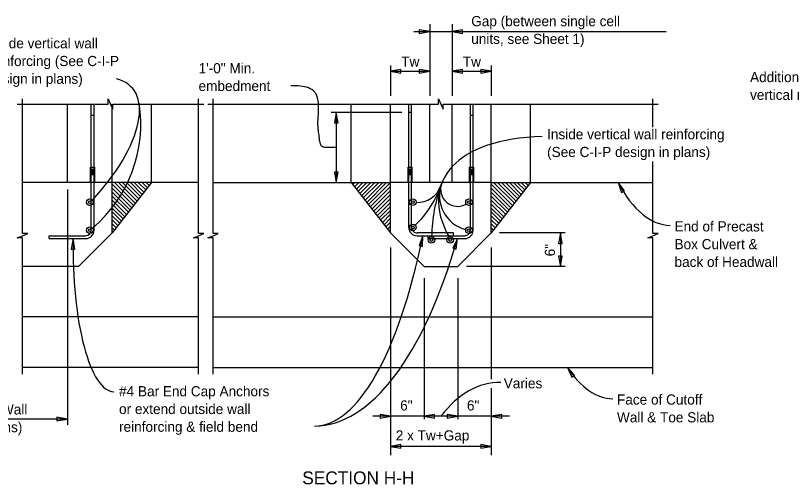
# Model space of a CAD drawing. Extents: x 10605.2 to 10672.7, y 76423.8 to 76450.2.
# Drawn here: x 10627.65 to 10639.2, y 76440.07 to 76447.04 of the extents above; entities that cross this region are included whole.
import ezdxf

# ---------------------------------------------------------------- set-up
doc = ezdxf.new("R2010")
doc.units = 0
for name, color, linetype in [('AdhocPoint_dp', 7, 'Continuous'), ('Patterning', 7, 'Continuous'), ('PlotBorder_dp', 7, 'Continuous'), ('SheetBorder_dp', 7, 'Continuous'), ('SheetLines_dp', 7, 'Continuous'), ('TextMisc', 7, 'Continuous')]:
    doc.layers.add(name, color=color, linetype=linetype)

msp = doc.modelspace()

# ---------------------------------------------------------------- linework, layer by layer
at = {"layer": 'AdhocPoint_dp'}
for p, q in [((10633.814, 76446.912), (10633.814, 76445.847)), ((10634.148, 76446.912), (10634.148, 76445.847)), ((10633.578, 76446.802), (10633.814, 76446.802)), ((10633.814, 76446.802), (10634.148, 76446.802)), ((10634.148, 76446.802), (10637.331, 76446.802)), ((10633.231, 76446.298), (10633.231, 76445.847)), ((10634.731, 76446.298), (10634.731, 76445.847)), ((10633.231, 76446.214), (10633.814, 76446.214)), ((10634.148, 76446.214), (10634.731, 76446.214)), ((10637.136, 76445.379), (10637.136, 76445.802)), ((10633.402, 76445.6), (10632.347, 76445.6)), ((10632.424, 76445.6), (10632.424, 76444.558)), ((10628.424, 76444.453), (10628.424, 76440.952)), ((10635.831, 76443.808), (10634.854, 76443.808)), ((10635.759, 76443.808), (10635.759, 76443.308)), ((10633.231, 76443.593), (10633.231, 76440.503)), ((10634.731, 76443.593), (10634.731, 76441.633)), ((10635.831, 76443.308), (10634.362, 76443.308)), ((10633.731, 76443.135), (10633.731, 76441.038)), ((10634.231, 76443.135), (10634.231, 76441.038)), ((10634.731, 76441.498), (10634.731, 76440.503)), ((10633.231, 76441.082), (10632.968, 76441.082)), ((10633.731, 76441.082), (10633.231, 76441.082)), ((10634.231, 76441.082), (10633.731, 76441.082)), ((10634.731, 76441.082), (10634.231, 76441.082)), ((10635.004, 76441.082), (10634.731, 76441.082)), ((10628.422, 76441.04), (10626, 76441.04)), ((10634.731, 76440.633), (10633.231, 76440.633))]:
    msp.add_line(p, q, dxfattribs=at)
for points in [[(10633.814, 76446.802), (10633.658, 76446.828), (10633.658, 76446.775)], [(10634.148, 76446.802), (10634.304, 76446.775), (10634.304, 76446.828)], [(10633.231, 76446.214), (10633.387, 76446.187), (10633.387, 76446.24)], [(10633.814, 76446.214), (10633.658, 76446.24), (10633.658, 76446.187)], [(10634.148, 76446.214), (10634.304, 76446.187), (10634.304, 76446.24)], [(10634.731, 76446.214), (10634.575, 76446.24), (10634.575, 76446.187)], [(10632.424, 76445.6), (10632.397, 76445.444), (10632.45, 76445.444)], [(10632.424, 76444.558), (10632.45, 76444.714), (10632.397, 76444.714)], [(10636.617, 76444.558), (10636.667, 76444.408), (10636.713, 76444.432)], [(10628.508, 76443.725), (10628.479, 76443.569), (10628.532, 76443.568)], [(10633.714, 76443.766), (10633.656, 76443.619), (10633.708, 76443.608)], [(10634.227, 76443.725), (10634.159, 76443.582), (10634.209, 76443.567)], [(10635.759, 76443.808), (10635.733, 76443.652), (10635.786, 76443.652)], [(10635.759, 76443.308), (10635.786, 76443.464), (10635.733, 76443.464)], [(10635.863, 76441.808), (10635.927, 76441.663), (10635.971, 76441.692)], [(10628.422, 76441.04), (10628.266, 76441.067), (10628.266, 76441.014)], [(10633.231, 76441.082), (10633.075, 76441.108), (10633.075, 76441.055)], [(10633.731, 76441.082), (10633.887, 76441.055), (10633.887, 76441.108)], [(10634.231, 76441.082), (10634.075, 76441.108), (10634.075, 76441.055)], [(10634.731, 76441.082), (10634.887, 76441.055), (10634.887, 76441.108)], [(10633.231, 76440.633), (10633.387, 76440.607), (10633.387, 76440.66)], [(10634.731, 76440.633), (10634.575, 76440.66), (10634.575, 76440.607)]]:
    msp.add_lwpolyline(points, close=True, dxfattribs=at)
for points in [[(10627.756, 76441.709), (10627.756, 76443.733), (10627.678, 76443.733), (10627.756, 76443.766), (10627.833, 76443.8), (10627.756, 76443.8), (10627.756, 76445.802)], [(10627.678, 76445.725), (10629.032, 76445.725), (10629.032, 76445.802), (10629.065, 76445.725), (10629.099, 76445.647), (10629.099, 76445.725), (10630.453, 76445.725)], [(10630.375, 76441.709), (10630.375, 76443.733), (10630.298, 76443.733), (10630.375, 76443.766), (10630.453, 76443.8), (10630.375, 76443.8), (10630.375, 76445.802)], [(10630.514, 76445.725), (10633.947, 76445.725), (10633.947, 76445.802), (10633.981, 76445.725), (10634.015, 76445.647), (10634.015, 76445.725), (10637.214, 76445.725)], [(10630.592, 76441.709), (10630.592, 76443.733), (10630.514, 76443.733), (10630.592, 76443.766), (10630.669, 76443.8), (10630.592, 76443.8), (10630.592, 76445.802)], [(10637.136, 76441.709), (10637.136, 76443.733), (10637.059, 76443.733), (10637.136, 76443.766), (10637.214, 76443.8), (10637.136, 76443.8), (10637.136, 76444.871)]]:
    msp.add_lwpolyline(points, dxfattribs=at)
for centre in [(10628.758, 76444.266), (10633.564, 76444.266), (10634.398, 76444.266), (10633.564, 76443.891), (10628.758, 76443.85), (10634.398, 76443.85), (10633.842, 76443.704), (10634.12, 76443.704)]:
    msp.add_circle(centre, 0.0484, dxfattribs=at)
for centre, radius, start, end in [((10627.501, 76445.421), 2.014, 310.0351, 9.0815), ((10632.562, 76445.014), 1.505, 313.6067, 341.4608), ((10633.625, 76444.638), 0.377, 268.0838, 340.54), ((10636.262, 76443.706), 2.42, 159.9499, 178.8939), ((10634.477, 76444.362), 0.518, 159.2154, 255.8414), ((10634.23, 76444.456), 0.253, 159.2154, 300.6523)]:
    msp.add_arc(centre, radius, start, end, dxfattribs=at)
for centre, major_axis, ratio, start_param, end_param in [((10627.995, 76444.702), (-1.388, -1.268), 0.452293, 1.740338, 3.438697), ((10636.833, 76443.553), (2.849, -0.969), 0.486344, 2.219026, 3.635956), ((10637.435, 76446.81), (0.044, 2.889), 0.436833, 2.471547, 3.141593), ((10629.13, 76443.648), (0.017, 2.202), 0.282679, 1.537886, 3.141593), ((10631.976, 76448.377), (-0.124, 7.444), 0.285208, 3.141593, 4.03961), ((10631.976, 76448.377), (-0.124, 7.444), 0.375791, 3.141593, 4.03097), ((10636.581, 76444.231), (0.044, 2.889), 0.436833, 2.572127, 3.141593), ((10634.827, 76439.651), (-0.047, -1.933), 0.665458, 3.141593, 3.895381)]:
    msp.add_ellipse(centre, major_axis=major_axis, ratio=ratio, start_param=start_param, end_param=end_param, dxfattribs=at)
msp.add_spline([(10632.424, 76445.079), (10632.341, 76445.079), (10632.253, 76445.079), (10632.206, 76445.1), (10632.186, 76445.145), (10632.18, 76445.167), (10632.174, 76445.2), (10632.168, 76445.268), (10632.162, 76445.305), (10632.154, 76445.366), (10632.084, 76445.923), (10631.859, 76445.995), (10631.748, 76445.995)], degree=3, dxfattribs=at)
at = {"layer": 'Patterning'}
for p, q in [((10628.779, 76445.558), (10628.779, 76445.725)), ((10628.82, 76445.558), (10628.82, 76445.725)), ((10633.502, 76445.558), (10633.502, 76445.725)), ((10633.544, 76445.558), (10633.544, 76445.725)), ((10634.419, 76445.558), (10634.419, 76445.725)), ((10634.46, 76445.558), (10634.46, 76445.725)), ((10628.779, 76443.85), (10628.779, 76445.558)), ((10628.779, 76445.558), (10628.82, 76445.558)), ((10628.82, 76443.85), (10628.82, 76445.558)), ((10633.502, 76443.891), (10633.502, 76445.6)), ((10633.544, 76445.6), (10633.502, 76445.6)), ((10633.544, 76443.891), (10633.544, 76445.6)), ((10634.419, 76443.85), (10634.419, 76445.558)), ((10634.419, 76445.558), (10634.46, 76445.558)), ((10634.46, 76443.85), (10634.46, 76445.558)), ((10628.154, 76443.725), (10628.154, 76443.766)), ((10628.154, 76443.766), (10628.695, 76443.766)), ((10628.154, 76443.725), (10628.695, 76443.725)), ((10634.169, 76443.808), (10633.627, 76443.808)), ((10633.627, 76443.766), (10634.335, 76443.766)), ((10633.793, 76443.725), (10633.793, 76443.766)), ((10633.793, 76443.725), (10634.335, 76443.725)), ((10634.169, 76443.766), (10634.169, 76443.808))]:
    msp.add_line(p, q, dxfattribs=at)
for centre in [(10628.758, 76444.266), (10633.564, 76444.266), (10634.398, 76444.266), (10628.758, 76443.85), (10633.564, 76443.891), (10634.398, 76443.85), (10633.842, 76443.704), (10634.12, 76443.704)]:
    msp.add_circle(centre, 0.0208, dxfattribs=at)
for centre, radius, start, end in [((10628.695, 76443.85), 0.0833, 270.002, 0.0007), ((10628.695, 76443.85), 0.125, 270.0048, 0.0009), ((10633.627, 76443.891), 0.125, 179.9945, 269.9955), ((10633.627, 76443.891), 0.0833, 179.996, 270), ((10634.335, 76443.85), 0.0833, 270, 0.0007), ((10634.335, 76443.85), 0.125, 270, 0.0009)]:
    msp.add_arc(centre, radius, start, end, dxfattribs=at)
at = {"layer": 'PlotBorder_dp'}
for p, q in [((10629.091, 76443.808), (10629.091, 76444.558)), ((10629.674, 76444.558), (10629.091, 76443.808)), ((10629.091, 76444.533), (10629.408, 76444.216)), ((10629.125, 76444.558), (10629.434, 76444.249)), ((10629.184, 76444.558), (10629.46, 76444.282)), ((10629.243, 76444.558), (10629.486, 76444.315)), ((10629.302, 76444.558), (10629.511, 76444.348)), ((10629.361, 76444.558), (10629.537, 76444.381)), ((10629.419, 76444.558), (10629.563, 76444.415)), ((10629.478, 76444.558), (10629.589, 76444.448)), ((10629.537, 76444.558), (10629.614, 76444.481)), ((10629.596, 76444.558), (10629.64, 76444.514)), ((10629.655, 76444.558), (10629.666, 76444.547)), ((10632.648, 76444.558), (10633.231, 76443.808)), ((10632.672, 76444.527), (10632.702, 76444.558)), ((10632.697, 76444.494), (10632.761, 76444.558)), ((10632.723, 76444.461), (10632.82, 76444.558)), ((10632.749, 76444.428), (10632.879, 76444.558)), ((10632.775, 76444.395), (10632.938, 76444.558)), ((10632.8, 76444.362), (10632.997, 76444.558)), ((10632.826, 76444.329), (10633.056, 76444.558)), ((10632.852, 76444.295), (10633.115, 76444.558)), ((10632.878, 76444.262), (10633.173, 76444.558)), ((10632.904, 76444.229), (10633.231, 76444.557)), ((10633.231, 76443.808), (10633.231, 76444.558)), ((10634.731, 76444.558), (10633.231, 76444.558)), ((10634.731, 76443.808), (10634.731, 76444.558)), ((10635.314, 76444.558), (10634.731, 76443.808)), ((10634.731, 76444.533), (10635.048, 76444.216)), ((10634.765, 76444.558), (10635.074, 76444.249)), ((10634.824, 76444.558), (10635.1, 76444.282)), ((10634.883, 76444.558), (10635.125, 76444.315)), ((10634.942, 76444.558), (10635.151, 76444.348)), ((10635, 76444.558), (10635.177, 76444.381)), ((10635.059, 76444.558), (10635.203, 76444.415)), ((10635.118, 76444.558), (10635.229, 76444.448)), ((10635.177, 76444.558), (10635.254, 76444.481)), ((10635.236, 76444.558), (10635.28, 76444.514)), ((10635.295, 76444.558), (10635.306, 76444.547)), ((10629.091, 76444.474), (10629.382, 76444.183)), ((10629.091, 76444.415), (10629.357, 76444.149)), ((10632.929, 76444.196), (10633.231, 76444.498)), ((10632.955, 76444.163), (10633.231, 76444.439)), ((10634.731, 76444.474), (10635.022, 76444.183)), ((10634.731, 76444.415), (10634.997, 76444.149)), ((10629.091, 76444.356), (10629.331, 76444.116)), ((10629.091, 76444.297), (10629.305, 76444.083)), ((10632.981, 76444.13), (10633.231, 76444.38)), ((10633.007, 76444.097), (10633.231, 76444.321)), ((10634.731, 76444.356), (10634.971, 76444.116)), ((10634.731, 76444.297), (10634.945, 76444.083)), ((10629.091, 76444.238), (10629.279, 76444.05)), ((10629.091, 76444.179), (10629.254, 76444.017)), ((10633.032, 76444.063), (10633.231, 76444.262)), ((10633.058, 76444.03), (10633.231, 76444.203)), ((10634.731, 76444.238), (10634.919, 76444.05)), ((10634.731, 76444.179), (10634.893, 76444.017)), ((10629.091, 76444.12), (10629.228, 76443.984)), ((10629.091, 76444.061), (10629.202, 76443.951)), ((10633.084, 76443.997), (10633.231, 76444.144)), ((10633.11, 76443.964), (10633.231, 76444.085)), ((10634.731, 76444.12), (10634.868, 76443.984)), ((10634.731, 76444.061), (10634.842, 76443.951)), ((10629.091, 76444.002), (10629.176, 76443.917)), ((10629.091, 76443.944), (10629.15, 76443.884)), ((10633.136, 76443.931), (10633.231, 76444.026)), ((10633.161, 76443.898), (10633.231, 76443.967)), ((10634.731, 76444.002), (10634.816, 76443.917)), ((10634.731, 76443.944), (10634.79, 76443.884)), ((10629.091, 76443.885), (10629.125, 76443.851)), ((10629.091, 76443.826), (10629.099, 76443.818)), ((10633.187, 76443.865), (10633.231, 76443.909)), ((10633.213, 76443.831), (10633.231, 76443.85)), ((10634.731, 76443.885), (10634.765, 76443.851)), ((10634.731, 76443.826), (10634.739, 76443.818)), ((10628.591, 76443.308), (10629.091, 76443.808)), ((10633.731, 76443.308), (10633.231, 76443.808)), ((10634.231, 76443.308), (10634.731, 76443.808)), ((10628.591, 76443.308), (10627.756, 76443.308)), ((10633.731, 76443.308), (10634.231, 76443.308)), ((10633.731, 76443.308), (10634.231, 76443.308)), ((10630.375, 76441.808), (10627.756, 76441.808)), ((10630.592, 76441.808), (10637.136, 76441.808))]:
    msp.add_line(p, q, dxfattribs=at)
at = {"layer": 'SheetLines_dp'}
for p, q in [((10628.768, 76444.558), (10628.768, 76444.787)), ((10628.779, 76444.715), (10628.779, 76444.755)), ((10628.779, 76444.755), (10628.82, 76444.755)), ((10628.779, 76444.745), (10628.82, 76444.745)), ((10628.82, 76444.715), (10628.82, 76444.755)), ((10628.83, 76444.558), (10628.83, 76444.787)), ((10633.492, 76444.558), (10633.492, 76444.787)), ((10633.502, 76444.715), (10633.502, 76444.755)), ((10633.502, 76444.755), (10633.544, 76444.755)), ((10633.502, 76444.745), (10633.544, 76444.745)), ((10633.544, 76444.715), (10633.544, 76444.755)), ((10633.554, 76444.558), (10633.554, 76444.787)), ((10634.408, 76444.558), (10634.408, 76444.787)), ((10634.419, 76444.715), (10634.419, 76444.755)), ((10634.419, 76444.755), (10634.46, 76444.755)), ((10634.419, 76444.745), (10634.46, 76444.745)), ((10634.46, 76444.715), (10634.46, 76444.755)), ((10634.47, 76444.558), (10634.47, 76444.787)), ((10628.779, 76444.735), (10628.82, 76444.735)), ((10628.779, 76444.725), (10628.82, 76444.725)), ((10628.779, 76444.675), (10628.779, 76444.715)), ((10628.779, 76444.715), (10628.82, 76444.715)), ((10628.779, 76444.705), (10628.82, 76444.705)), ((10628.779, 76444.695), (10628.82, 76444.695)), ((10628.779, 76444.685), (10628.82, 76444.685)), ((10628.779, 76444.675), (10628.82, 76444.675)), ((10628.82, 76444.675), (10628.82, 76444.715)), ((10633.502, 76444.735), (10633.544, 76444.735)), ((10633.502, 76444.725), (10633.544, 76444.725)), ((10633.502, 76444.675), (10633.502, 76444.715)), ((10633.502, 76444.715), (10633.544, 76444.715)), ((10633.502, 76444.705), (10633.544, 76444.705)), ((10633.502, 76444.695), (10633.544, 76444.695)), ((10633.502, 76444.685), (10633.544, 76444.685)), ((10633.502, 76444.675), (10633.544, 76444.675)), ((10633.544, 76444.675), (10633.544, 76444.715)), ((10634.419, 76444.735), (10634.46, 76444.735)), ((10634.419, 76444.725), (10634.46, 76444.725)), ((10634.419, 76444.675), (10634.419, 76444.715)), ((10634.419, 76444.715), (10634.46, 76444.715)), ((10634.419, 76444.705), (10634.46, 76444.705)), ((10634.419, 76444.695), (10634.46, 76444.695)), ((10634.419, 76444.685), (10634.46, 76444.685)), ((10634.419, 76444.675), (10634.46, 76444.675)), ((10634.46, 76444.675), (10634.46, 76444.715))]:
    msp.add_line(p, q, dxfattribs=at)
for points in [[(10628.768, 76444.787), (10628.83, 76444.787)], [(10633.492, 76444.787), (10633.554, 76444.787)], [(10634.408, 76444.787), (10634.47, 76444.787)]]:
    msp.add_lwpolyline(points, dxfattribs=at)
at = {"layer": 'TextMisc'}
for p, q in [((10628.424, 76444.558), (10628.424, 76445.725)), ((10629.091, 76444.558), (10629.091, 76445.725)), ((10629.674, 76444.558), (10629.674, 76445.725)), ((10632.648, 76444.558), (10632.648, 76445.725)), ((10633.231, 76444.558), (10633.231, 76445.725)), ((10633.814, 76444.558), (10633.814, 76445.725)), ((10634.148, 76444.558), (10634.148, 76445.725)), ((10634.731, 76444.558), (10634.731, 76445.725)), ((10635.314, 76444.558), (10635.314, 76445.725)), ((10630.375, 76444.558), (10627.756, 76444.558)), ((10630.592, 76444.558), (10633.231, 76444.558)), ((10634.731, 76444.558), (10637.136, 76444.558)), ((10630.375, 76442.558), (10627.756, 76442.558)), ((10630.592, 76442.558), (10637.136, 76442.558))]:
    msp.add_line(p, q, dxfattribs=at)

# ---------------------------------------------------------------- texts
at = {"layer": 'AdhocPoint_dp'}
for s, p in [('Gap (between single cell', (10634.432, 76446.883)), ('Inside vertical wall', (10627.236, 76446.554)), ('units, see Sheet 1)', (10634.432, 76446.619)), ('reinforcing (See C-I-P', (10627.236, 76446.29)), ('1\'-0" Min.', (10630.375, 76446.183)), ('design in plans)', (10627.236, 76446.026)), ('Additional outside', (10638.581, 76446.051)), ('embedment', (10630.375, 76445.919)), ('vertical reinforcing', (10638.581, 76445.787)), ('Inside vertical wall reinforcing', (10635.561, 76445.201)), ('(See C-I-P design in plans)', (10635.561, 76444.937)), ('End of Precast', (10637.457, 76443.83)), ('Box Culvert &', (10637.457, 76443.566)), ('back of Headwall', (10637.457, 76443.302)), ('#4 Bar End Cap Anchors', (10629.192, 76441.378)), ('Face of Cutoff', (10636.601, 76441.254)), ('C-I-P Wing Wall', (10626.39, 76441.108)), ('or extend outside wall', (10629.192, 76441.114)), ('Wall & Toe Slab', (10636.601, 76440.99)), ('(As per Plans)', (10626.472, 76440.844)), ('reinforcing & field bend', (10629.192, 76440.85))]:
    msp.add_text(s, height=0.1512, dxfattribs=at).set_placement(p)
at = {"layer": 'SheetBorder_dp'}
for s, height, p in [('Tw', 0.1512, (10633.391, 76446.28)), ('Tw', 0.1512, (10634.307, 76446.28)), ('Varies', 0.1512, (10634.916, 76441.496)), ('6"', 0.1512, (10633.375, 76441.167)), ('6"', 0.1512, (10634.368, 76441.167)), ('2 x Tw+Gap', 0.1512, (10633.309, 76440.721)), ('SECTION H-H', 0.192, (10631.918, 76440.069))]:
    msp.add_text(s, height=height, dxfattribs=at).set_placement(p)
msp.add_text('6"', height=0.1512, rotation=90, dxfattribs=at).set_placement((10635.679, 76443.46))

doc.saveas('drawing.dxf')
